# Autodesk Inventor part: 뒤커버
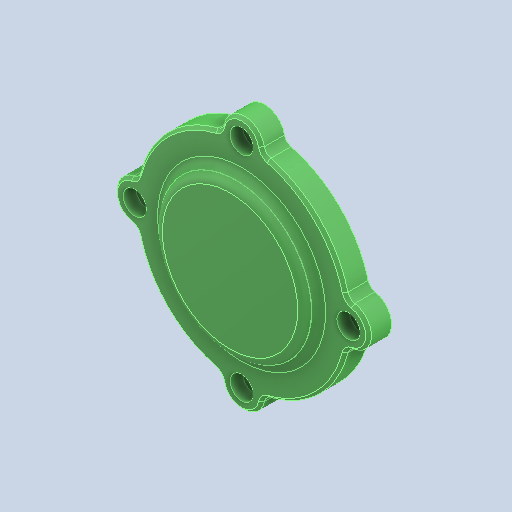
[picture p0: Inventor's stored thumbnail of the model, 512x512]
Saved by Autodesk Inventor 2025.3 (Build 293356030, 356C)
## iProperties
Created: 2025-08
Part Number: 뒤커버
Material: 알루미늄 6061
Document SubType Name: Modeling
Designer: infra011
Density: 2.71 g/cm^3
Appearance: 기본값
Company: 한국ATC센터
Author: jhkim
Sending System: Autodesk Inventor 2026
Preprocessor: ST-DEVELOPER v20.1
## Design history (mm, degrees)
feature "솔리드1"
node "솔리드2"
